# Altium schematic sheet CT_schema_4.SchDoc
size 445 x 328 mm
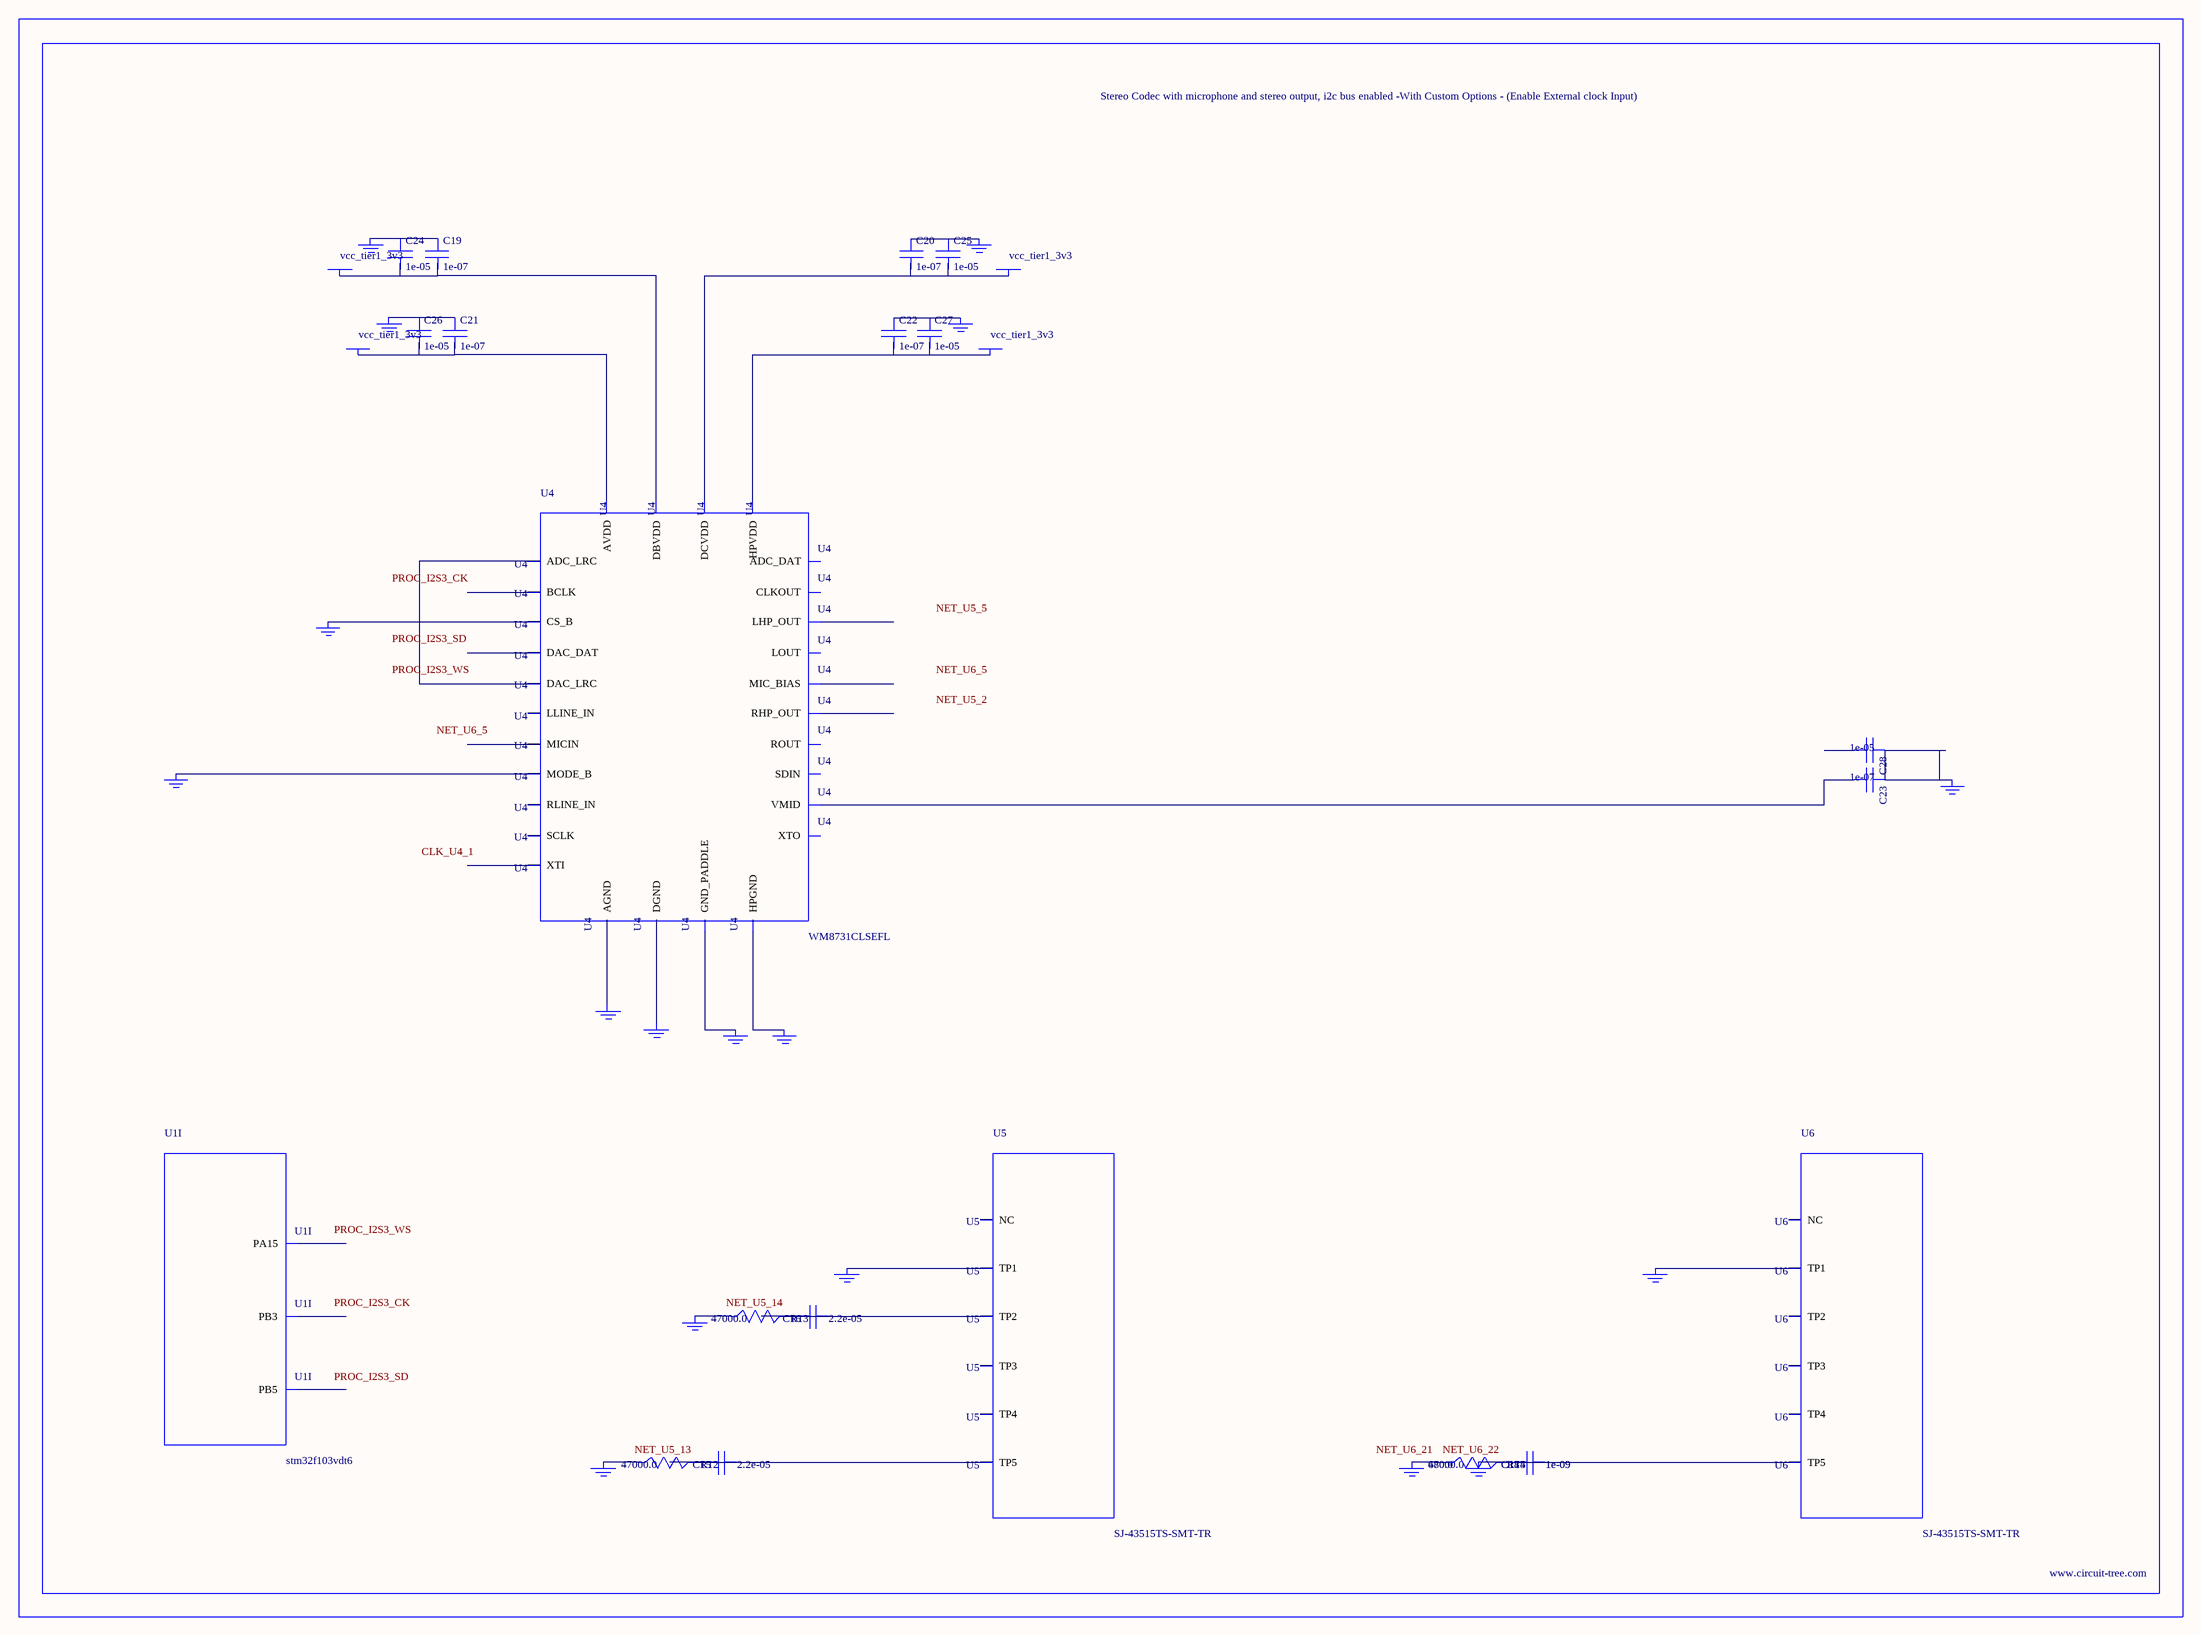
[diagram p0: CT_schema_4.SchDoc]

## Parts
BORDER3  (no value)
C15  2.2e-05  [C1210]
C16  2.2e-05  [C1210]
C17  1e-09  [C0402]
C18  1e-09  [C0402]
C19  1e-07  [C0402]
C20  1e-07  [C0402]
C21  1e-07  [C0402]
C22  1e-07  [C0402]
C23  1e-07  [C0402]
C24  1e-05  [C0805]
C25  1e-05  [C0805]
C26  1e-05  [C0805]
C27  1e-05  [C0805]
C28  1e-05  [C0805]
GND_INSTANCE_3_0  (no value)
GND_INSTANCE_3_1  (no value)
GND_INSTANCE_3_2  (no value)
GND_INSTANCE_3_3  (no value)
GND_INSTANCE_3_4  (no value)
GND_INSTANCE_3_5  (no value)
GND_INSTANCE_3_6  (no value)
GND_INSTANCE_3_7  (no value)
GND_INSTANCE_3_8  (no value)
GND_INSTANCE_3_9  (no value)
GND_INSTANCE_3_10  (no value)
GND_INSTANCE_3_11  (no value)
GND_INSTANCE_3_12  (no value)
GND_INSTANCE_3_13  (no value)
GND_INSTANCE_3_14  (no value)
GND_INSTANCE_3_15  (no value)
GND_INSTANCE_3_16  (no value)
POWER_INSTANCE_3_0  vcc_tier1_3v3
POWER_INSTANCE_3_1  vcc_tier1_3v3
POWER_INSTANCE_3_2  vcc_tier1_3v3
POWER_INSTANCE_3_3  vcc_tier1_3v3
R12  47000.0  [R0603]
R13  47000.0  [R0603]
R14  47000.0  [R0603]
R15  680.0  [R0603]
U1  stm32f103vdt6  [LQFP100]  (part I of 9)
U4  WM8731CLSEFL  [QFN-28]
U5  SJ-43515TS-SMT-TR  [SJ-43515TS-SMT-TR]
U6  SJ-43515TS-SMT-TR  [SJ-43515TS-SMT-TR]

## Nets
NetC15_1: C15.1 C15.2 R12.2 U5.5(TP5)
NetC16_1: C16.1 C16.2 R13.2 U5.2(TP2)
NetC17_1: C17.1 C17.2 C18.1 C18.2 GND_INSTANCE_3_16.0(GND) R14.2 R15.2 U6.5(TP5)
NetC19_1: C19.1 C24.1 GND_INSTANCE_3_1.0(GND)
NetC19_2: C19.2 C24.2 POWER_INSTANCE_3_1.0(PWR) U4.5(DBVDD)
NetC20_1: C20.1 C25.1 GND_INSTANCE_3_0.0(GND)
NetC20_2: C20.2 C25.2 POWER_INSTANCE_3_0.0(PWR) U4.3(DCVDD)
NetC21_1: C21.1 C26.1 GND_INSTANCE_3_4.0(GND)
NetC21_2: C21.2 C26.2 POWER_INSTANCE_3_3.0(PWR) U4.18(AVDD)
NetC22_1: C22.1 C27.1 GND_INSTANCE_3_2.0(GND)
NetC22_2: C22.2 C27.2 POWER_INSTANCE_3_2.0(PWR) U4.12(HPVDD)
NetC23_1: C23.1 C28.1 GND_INSTANCE_3_5.0(GND)
NetC23_2: C23.2 U4.20(VMID)
NetGND_INSTANCE_3_3_0: GND_INSTANCE_3_3.0(GND) U4.15(HPGND)
NetGND_INSTANCE_3_6_0: GND_INSTANCE_3_6.0(GND) U4.25(MODE_B)
NetGND_INSTANCE_3_7_0: GND_INSTANCE_3_7.0(GND) U4.26(CS_B)
NetGND_INSTANCE_3_8_0: GND_INSTANCE_3_8.0(GND) U4.29(GND_PADDLE)
NetGND_INSTANCE_3_9_0: GND_INSTANCE_3_9.0(GND) U4.4(DGND)
NetGND_INSTANCE_3_10_0: GND_INSTANCE_3_10.0(GND) U4.19(AGND)
NetGND_INSTANCE_3_11_0: GND_INSTANCE_3_11.0(GND) U5.1(TP1)
NetGND_INSTANCE_3_12_0: GND_INSTANCE_3_12.0(GND) R13.1
NetGND_INSTANCE_3_13_0: GND_INSTANCE_3_13.0(GND) R12.1
NetGND_INSTANCE_3_14_0: GND_INSTANCE_3_14.0(GND) U6.1(TP1)
NetGND_INSTANCE_3_15_0: GND_INSTANCE_3_15.0(GND) R14.1 R15.1
NetU4_9: U4.9(DAC_LRC) U4.11(ADC_LRC)

Not connected (* = marked no-connect by the designer): C28 2; U1 77(PA15) 89(PB3) 91(PB5); U4 1(XTI) 2(XTO) 6(CLKOUT) 7(BCLK) 8(DAC_DAT) 10(ADC_DAT) 13(LHP_OUT) 14(RHP_OUT) 16(LOUT) 17(ROUT) 21(MIC_BIAS) 22(MICIN) 23(RLINE_IN) 24(LLINE_IN) 27(SDIN) 28(SCLK); U5 3(TP3) 4(TP4) 6(NC); U6 2(TP2) 3(TP3) 4(TP4) 6(NC)

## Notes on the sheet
- Labels drawn without touching a wire or pin: CLK_U4_1, NET_U5_2, NET_U5_5, NET_U5_13, NET_U5_14, NET_U6_5, NET_U6_21, NET_U6_22, PROC_I2S3_CK, PROC_I2S3_SD, PROC_I2S3_WS

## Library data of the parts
BORDER3 = BORDER_PAGE3
C15 C16 = C1210C224K5RACTU
C17 C18 = C0402C102K3RAC
C19-C23 = C0402C104K3RACTU
C24-C28 = C0805C106K8RACTU
GND_INSTANCE_3_0-GND_INSTANCE_3_16 = GND
POWER_INSTANCE_3_0-POWER_INSTANCE_3_3 = PWR
R12-R14 = RC0603JR-0747KL
R15 = RC0603JR-07680RL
